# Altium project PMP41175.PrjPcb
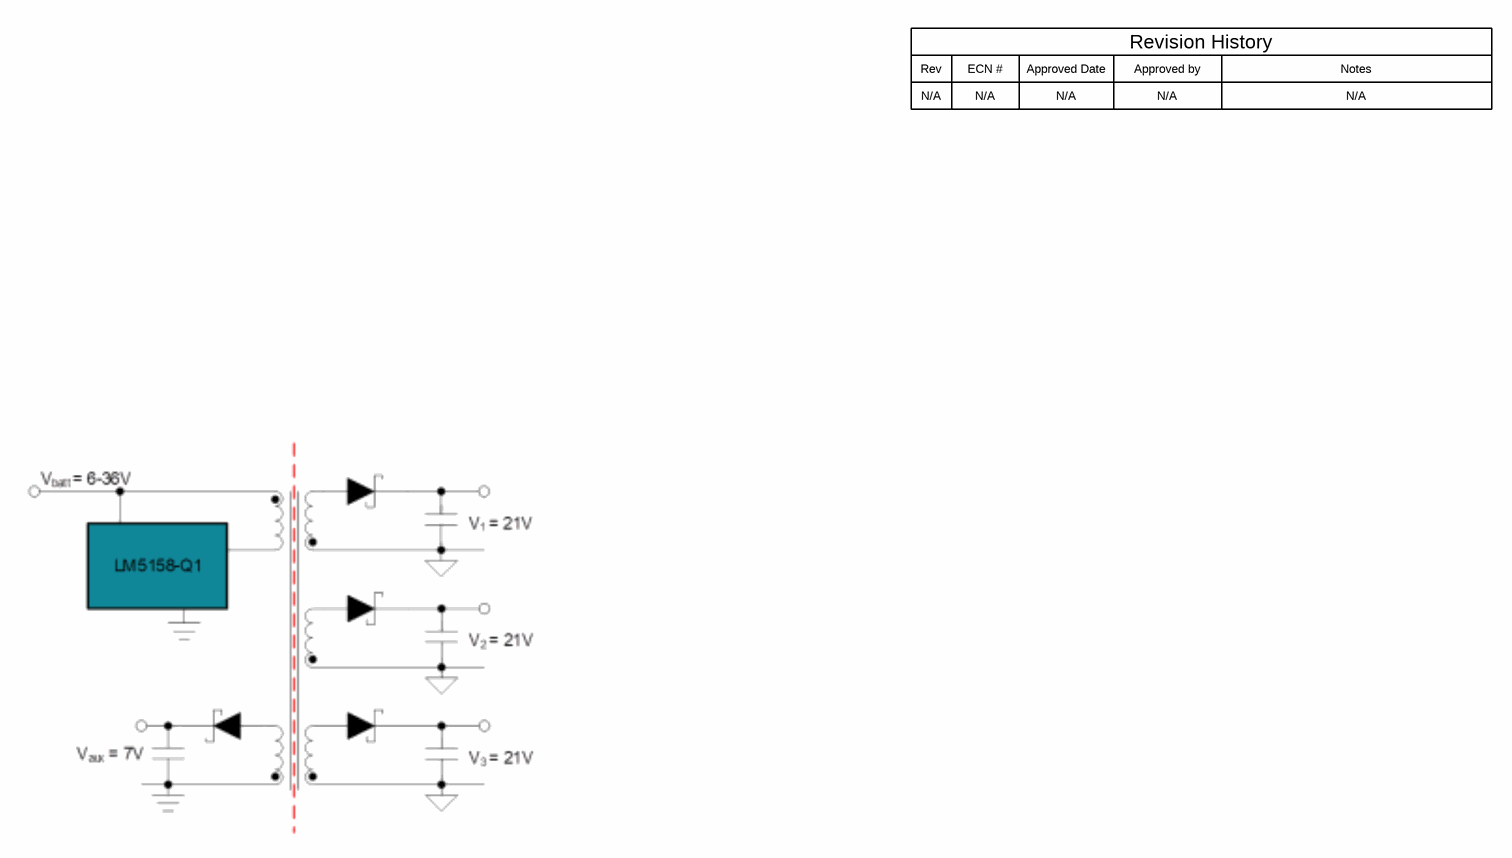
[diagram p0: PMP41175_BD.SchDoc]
CopyrightYear: 2025; PCB_Layout: Helmlinger; PCB_Rev: E1; PRJ_Customer: Public Release; PRJ_Engineer: Helmlinger; PRJ_Number: PMP41175; PRJ_Title: Flyback with planar XFMR; SCH_Rev: E1; TechSupport: http://www.ti.com/support; TID: N/A
3 sheets, 58 parts. Net scope: global (net labels, ports and power ports of the same name join across sheets).
Board file: PMP41175.PcbDoc
Sheets:
  PMP41175_BD.SchDoc
  PMP41175_Sheet1.SchDoc
  PMP41175_Hardware.SchDoc

## Sheet PMP41175_BD.SchDoc
size 431 x 279 mm; Date: Not shown in title block; ApprovedBy: Not shown in title block; CheckedBy: Not shown in title block; Author: Not shown in title block; CompanyName: Not shown in title block; Engineer: Not shown in title block; Organization: Not shown in title block; Address1: Not shown in title block; Address2: Not shown in title block; Address3: Not shown in title block; Address4: Not shown in title block; DocumentNumber: 1; Revision: Use project parameter SCH_Rev; SheetNumber: 1; SheetTotal: 3; PageSetup: Record=PageOptions¦CenterHorizontal=True¦CenterVertical=True¦PrintScale=1.00¦XCorrection=1.00¦YCorrection=1.00¦PrintKind=0¦BorderSize=5000000¦LeftOffset=0¦BottomOffset=0¦Orientation=2¦PaperLength=1000¦PaperWidth=1000¦Scale=100¦PaperSource=15¦PrintQuality=600¦MediaType=1¦DitherType=10¦PaperKind=Letter¦PrintScaleMode=1

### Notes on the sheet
- Rev
- N/A
- ECN #
- Approved Date
- Approved by
- Revision History
- Notes

## Sheet PMP41175_Sheet1.SchDoc
size 431 x 279 mm; Date: Not shown in title block; ApprovedBy: Not shown in title block; CheckedBy: Not shown in title block; Author: Not shown in title block; CompanyName: Not shown in title block; Engineer: Not shown in title block; Organization: Not shown in title block; Address1: Not shown in title block; Address2: Not shown in title block; Address3: Not shown in title block; Address4: Not shown in title block; DocumentNumber: 2; Revision: Use project parameter SCH_Rev; SheetNumber: 2; SheetTotal: 3; PageSetup: Record=PageOptions¦CenterHorizontal=True¦CenterVertical=True¦PrintScale=1.00¦XCorrection=1.00¦YCorrection=1.00¦PrintKind=0¦BorderSize=5000000¦LeftOffset=0¦BottomOffset=0¦Orientation=2¦PaperLength=1000¦PaperWidth=1000¦Scale=100¦PaperSource=15¦PrintQuality=600¦MediaType=1¦DitherType=10¦PaperKind=Letter¦PrintScaleMode=1
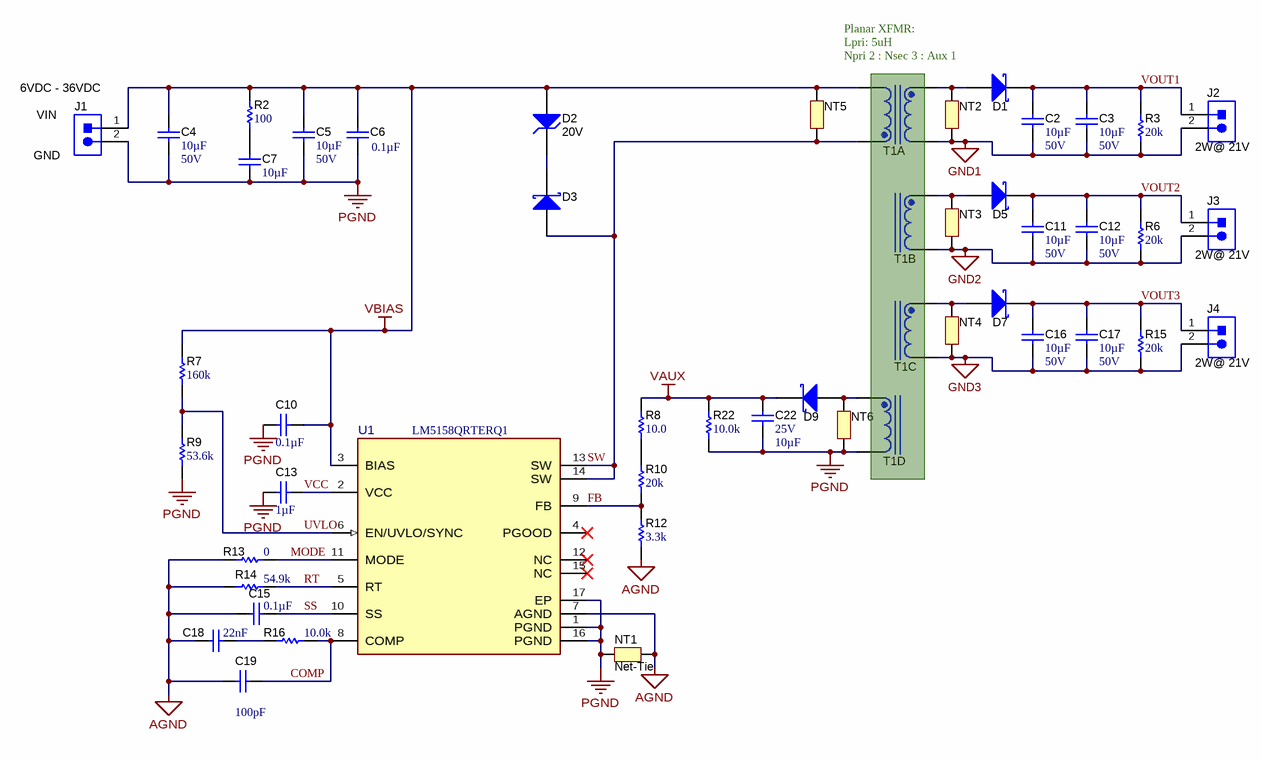
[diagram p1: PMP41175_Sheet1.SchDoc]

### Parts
C2  ValueDisplayed: 10µF  VDC_V: 50V  [1206_190]  (hidden comment: CGA5L1X7R1H106K160AC)
C3  ValueDisplayed: 10µF  VDC_V: 50V  [1206_190]  (hidden comment: CGA5L1X7R1H106K160AC)
C4  ValueDisplayed: 10µF  VDC_V: 50V  [1206_190]  (hidden comment: CGA5L1X7R1H106K160AC)
C5  ValueDisplayed: 10µF  VDC_V: 50V  [1206_190]  (hidden comment: CGA5L1X7R1H106K160AC)
C6  ValueDisplayed: 0.1µF  [0603L]  (hidden comment: C0603C104K5RACAUTO)
C7  ValueDisplayed: 10µF  [1206_190]  (hidden comment: CGA5L1X7R1H106K160AC)
C10  ValueDisplayed: 0.1µF  [0603L]  (hidden comment: C0603C104K5RACAUTO)
C11  ValueDisplayed: 10µF  VDC_V: 50V  [1206_190]  (hidden comment: CGA5L1X7R1H106K160AC)
C12  ValueDisplayed: 10µF  VDC_V: 50V  [1206_190]  (hidden comment: CGA5L1X7R1H106K160AC)
C13  Cap_F: 1µF  [0603L]  (hidden comment: 06033C105KAT2A)
C15  ValueDisplayed: 0.1µF  [0603L]  (hidden comment: C0603C104K5RACAUTO)
C16  ValueDisplayed: 10µF  VDC_V: 50V  [1206_190]  (hidden comment: CGA5L1X7R1H106K160AC)
C17  ValueDisplayed: 10µF  VDC_V: 50V  [1206_190]  (hidden comment: CGA5L1X7R1H106K160AC)
C18  Cap_F: 22nF  [0603L]  (hidden comment: C0603C223K3RACTU)
C19  ValueDisplayed: 100pF  [0603L]  (hidden comment: GCM1885C1H101JA16J)
C22  VDC_V: 25V  ValueDisplayed: 10µF  [0603L]  (hidden comment: GRM188R61E106KA73D)
D1  PMEG10020ELRX  [SOD-123W]  (value not drawn)
D2  value 20V  [SMA]  (hidden comment: 3SMAJ5932B-TP)
D3  PMEG60T30ELRX  [SOD-123W]  (value not drawn)
D5  PMEG10020ELRX  [SOD-123W]  (value not drawn)
D7  PMEG10020ELRX  [SOD-123W]  (value not drawn)
D9  PMEG10020ELRX  [SOD-123W]  (value not drawn)
J1  HTSW-102-09-G-S  [Samtec_HTSW-102-09-x-S]  (value not drawn)
J2  HTSW-102-09-G-S  [Samtec_HTSW-102-09-x-S]  (value not drawn)
J3  HTSW-102-09-G-S  [Samtec_HTSW-102-09-x-S]  (value not drawn)
J4  HTSW-102-09-G-S  [Samtec_HTSW-102-09-x-S]  (value not drawn)
NT1  Net-Tie  [Net-Tie_10mil]  (net tie, no BOM)
NT2  Net-Tie  [Net-Tie_10mil]  (value not drawn)  (net tie, no BOM)
NT3  Net-Tie  [Net-Tie_10mil]  (value not drawn)  (net tie, no BOM)
NT4  Net-Tie  [Net-Tie_10mil]  (value not drawn)  (net tie, no BOM)
NT5  Net-Tie  [Net-Tie_10mil]  (value not drawn)  (net tie, no BOM)
NT6  Net-Tie  [Net-Tie_10mil]  (value not drawn)  (net tie, no BOM)
R2  ValueDisplayed: 100  [0603L]  (hidden comment: CRCW0603100RFKEA)
R3  ValueDisplayed: 20k  [0603L]  (hidden comment: RC0603JR-0720KL)
R6  ValueDisplayed: 20k  [0603L]  (hidden comment: RC0603JR-0720KL)
R7  ValueDisplayed: 160k  [0603L]  (hidden comment: RC0603FR-07160KL)
R8  ValueDisplayed: 10.0  [0603L]  (hidden comment: RC0603FR-0710RL)
R9  ValueDisplayed: 53.6k  [0603L]  (hidden comment: RC0603FR-0753K6L)
R10  ValueDisplayed: 20k  [0603L]  (hidden comment: RC0603JR-0720KL)
R12  ValueDisplayed: 3.3k  [0603L]  (hidden comment: RC0603JR-073K3L)
R13  ValueDisplayed: 0  [0603L]  (hidden comment: ERJ-3GEY0R00V)
R14  ValueDisplayed: 54.9k  [0603L]  (hidden comment: RC0603FR-0754K9L)
R15  ValueDisplayed: 20k  [0603L]  (hidden comment: RC0603JR-0720KL)
R16  ValueDisplayed: 10.0k  [0603L]  (hidden comment: RC0603FR-0710KL)
R22  ValueDisplayed: 10.0k  [0603L]  (hidden comment: RC0603FR-0710KL)
T1  750345026  [PMP41104 Transformer]  (value not drawn)  (parts A,B,C,D of 5)
U1  LM5158QRTERQ1  [RTE0016K-MFG]

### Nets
AGND: C15.2 C18.2 C19.2 NT1.2 R12.1 R13.1 R14.1 U1.7(AGND)
GND1: C2.2 C3.2 J2.2 NT2.1 R3.1 T1.8
GND2: C11.2 C12.2 J3.2 NT3.1 R6.1 T1.14
GND3: C16.2 C17.2 J4.2 NT4.1 R15.1 T1.12
PGND: C4.2 C5.2 C6.2 C7.2 C10.2 C13.2 C22.2 J1.2 NT1.1 NT6.1 R9.2 R22.1 T1.6 U1.1(PGND) U1.16(PGND) U1.17(EP)
VAUX: C22.1 D9.1(K) R8.1 R22.2
VBIAS: C4.1 C5.1 C6.1 C10.1 D2.2(A) J1.1 NT5.2 R2.2 R7.1 T1.4 U1.3(BIAS)
COMP: C19.1 R16.2 U1.8(COMP)
FB: R10.1 R12.2 U1.9(FB)
MODE: R13.2 U1.11(MODE)
RT: R14.2 U1.5(RT)
SS: C15.1 U1.10(SS)
SW: D3.2(A) NT5.1 T1.2 U1.13(SW) U1.14(SW)
UVLO: R7.2 R9.1 U1.6(EN/UVLO/SYNC)
VCC: C13.1 U1.2(VCC)
VOUT1: C2.1 C3.1 D1.1(K) J2.1 R3.2
VOUT2: C11.1 C12.1 D5.1(K) J3.1 R6.2
VOUT3: C16.1 C17.1 D7.1(K) J4.1 R15.2
NetC7_1: C7.1 R2.1
NetC18_1: C18.1 R16.1
NetD1_2: D1.2(A) NT2.2 T1.7
NetD2_1: D2.1(K) D3.1(K)
NetD5_2: D5.2(A) NT3.2 T1.15
NetD7_2: D7.2(A) NT4.2 T1.13
NetD9_2: D9.2(A) NT6.2 T1.11
NetR8_2: R8.2 R10.2

Not connected (* = marked no-connect by the designer): U1 4(PGOOD)* 12(NC)* 15(NC)*

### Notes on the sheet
- (near J1) VIN
- (near J1) 6VDC - 36VDC
- (near T1) Planar XFMR:
  Lpri: 5uH
  Npri 2 : Nsec 3 : Aux 1
- (near J1) GND
- (near J2) 2W@ 21V
- (near J3) 2W@ 21V
- (near J4) 2W@ 21V

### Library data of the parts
C2-C5 C11 C12 C16 C17 = CMP-0085950-1: CAP, CERM, 10 µF, 50 V,+/- 10%, X7R, AEC-Q200 Grade 1, 1206; Manufacturer: TDK; SizeZ_mm: 1.9; Value: 10uF; Cap_Case: 1206; AEC Grade: 1; TaMin_C: -55°C; U/M: EA; SizeArea_mm2: 5.12; TaMax_C: 125°C; AEC Qualified: Y; AEC Category: Q200; SizeX_mm: 3.2; SizeY_mm: 1.6; Polarized: N; SizeAreaWB_mm2: 10.92
C6 C10 C15 = CMP-0079602-1: CAP, CERM, 0.1 µF, 50 V,+/- 10%, X7R, AEC-Q200 Grade 1, 0603; Manufacturer: Kemet; TaMin_C: -55°C; Polarized: N; SizeAreaWB_mm2: 4.68; U/M: EA; Value: 0.1uF; TaMax_C: 125°C; SizeZ_mm: 1; SizeX_mm: 1.6; SizeY_mm: 0.8; Cap_Case: 0603; Value2: 50V; SizeArea_mm2: 1.28; AEC Qualified: Y; Cap_F: 100nF; AEC Category: Q200
C7 = CMP-0085950-1: CAP, CERM, 10 µF, 50 V,+/- 10%, X7R, AEC-Q200 Grade 1, 1206; Manufacturer: TDK; SizeZ_mm: 1.9; Value: 10uF; Value2: 50V; Cap_Case: 1206; AEC Grade: 1; TaMin_C: -55°C; U/M: EA; SizeArea_mm2: 5.12; TaMax_C: 125°C; AEC Qualified: Y; AEC Category: Q200; SizeX_mm: 3.2; SizeY_mm: 1.6; Polarized: N; SizeAreaWB_mm2: 10.92
C13 = CMP-0006754-4: CAP, CERM, 1 uF, 25 V, +/- 10%, X7R, 0603; Manufacturer: AVX; TaMin_C: -55°C; Polarized: N; SizeAreaWB_mm2: 4.68; U/M: EA; Value: 1uF; TaMax_C: 125°C; SizeZ_mm: 1; SizeX_mm: 1.6; SizeY_mm: 0.8; Cap_Case: 0603; Value2: 25V; SizeArea_mm2: 1.28; AEC Category: Q200; Value1: Unknown
C18 = CMP-0006899-4: CAP, CERM, 0.022 uF, 25 V, +/- 10%, X7R, 0603; Manufacturer: Kemet; TaMin_C: -55°C; Polarized: N; SizeAreaWB_mm2: 4.68; Value1: Unknown; U/M: EA; TaMax_C: 125°C; SizeZ_mm: 1; SizeX_mm: 1.6; SizeY_mm: 0.8; Cap_Case: 0603; Value2: 25V; SizeArea_mm2: 1.28; AEC Category: Q200
C19 = CMP-0750041-1: CAP, CERM, 100 pF, 50 V,+/- 5%, C0G/NP0, AEC-Q200 Grade 1, 0603; Manufacturer: MuRata; AEC Grade: 1; SizeArea_mm2: 1.28; SizeX_mm: 1.6; Polarized: N; Cap_Case: 0603; TaMax_C: 125°C; Value2: 50V; Value: 100pF; U/M: EA; AEC Qualified: Y; SizeAreaWB_mm2: 4.68; TaMin_C: -55°C; SizeY_mm: 0.8; AEC Category: Q200
C22 = CMP-0860569-1: CAP, CERM, 10 µF, 25 V,+/- 10%, X5R, 0603; Manufacturer: MuRata; SizeZ_mm: 1; AEC Category: Q200; AEC Qualified: N; TaMin_C: -55°C; Cap_Case: 0603; SizeY_mm: 0.8; SizeAreaWB_mm2: 4.68; SizeArea_mm2: 1.28; TaMax_C: 85°C; SizeX_mm: 1.6; Value: 10uF; U/M: EA
D1 D5 D7 D9 = CMP-0028977-2: Diode, Schottky, 100 V, 2 A, AEC-Q101, SOD-123W; Manufacturer: Nexperia; SizeY_mm: 1.7; Value2: 0.83V; Vf_V: 830mV; SizeZ_mm: 1; SizeAreaWB_mm2: 12.15; Value1: 2A; Vr_V: 100V; TJmax_C: 175°C; SizeArea_mm2: 5.95; AEC Category: Q101; AEC Qualified: Y; Value: 100V; SizeX_mm: 3.5
D2 = CMP-0005511-4: Diode, Zener, 20 V, 3 W, SMA; Manufacturer: Micro Commercial Components; SizeArea_mm2: 16.3228; Power_W: 3W; SizeAreaWB_mm2: 37.3428; SizeY_mm: 2.92; AEC Category: Q101; RJA_CperW: 226; SizeZ_mm: 2.87; SizeX_mm: 5.59
D3 = CMP-0085903-1: Diode, Schottky, 60 V, 3 A, AEC-Q101, SOD-123W; Manufacturer: Nexperia; Vr_V: 60V; Value1: 3A; TJmax_C: 175°C; Value: 60V; SizeY_mm: 1.7; SizeZ_mm: 1; Vf_V: 620mV; SizeArea_mm2: 5.95; SizeX_mm: 3.5; Value2: 0.62V; SizeAreaWB_mm2: 12.15; AEC Category: Q101; AEC Qualified: Y
J1-J4 = CMP-0075626-1: Header, 100mil, 2x1, Gold, TH; Manufacturer: Samtec; Pitch_mm: 2.54; Gender: Male; Cert_CSA: Y; CT: False; Row_Count: 1
NT1-NT6 = CMP-0078142-6: Single point connection between nets.
R2 = CMP-0021991-4: RES, 100, 1%, 0.1 W, AEC-Q200 Grade 0, 0603; Manufacturer: Vishay-Dale; Power_W: 100mW; TempCo: 100 ppm/C; Value_Code: 100R; Value: 100; EIA_Code: E96; SizeX_mm: 1.6; SizeY_mm: 0.8; SizeZ_mm: 1; Value2: 0.1W; SizeArea_mm2: 1.28; AEC Qualified: Y; VDC_V: 75V; AEC Category: Q200; AEC Grade: 0
R3 R6 R10 R15 = CMP-0025900-5: RES, 20 k, 5%, 0.1 W, 0603; Manufacturer: Yageo; Power_W: 100mW; TempCo: 100 ppm/C; Value_Code: 20k0; Value: 20k; EIA_Code: E24; SizeX_mm: 1.6; SizeY_mm: 0.8; SizeZ_mm: 1; Value2: 0.1W; SizeArea_mm2: 1.28; AEC Qualified: N; VDC_V: 75V; AEC Category: Q200; SizeAreaWB_mm2: 4.68
R7 = CMP-0022820-4: RES, 160 k, 1%, 0.1 W, 0603; Manufacturer: Yageo; Value: 160k; SizeX_mm: 1.6; SizeY_mm: 0.8; SizeZ_mm: 1; Value2: 0.1W; SizeArea_mm2: 1.28; AEC Qualified: N; VDC_V: 75V; AEC Category: Q200; SizeAreaWB_mm2: 4.68; Power_W: 100mW; TempCo: 100 ppm/C
R8 = CMP-0022751-4: RES, 10.0, 1%, 0.1 W, 0603; Manufacturer: Yageo; Power_W: 100mW; TempCo: 100 ppm/C; Value_Code: 10R0; Value: 10.0; EIA_Code: E96; Res_ohm: 10; SizeX_mm: 1.6; SizeY_mm: 0.8; SizeZ_mm: 1; Value2: 0.1W; SizeArea_mm2: 1.28; AEC Qualified: N; VDC_V: 75V; AEC Category: Q200; SizeAreaWB_mm2: 4.68
R9 = CMP-0023176-5: RES, 53.6 k, 1%, 0.1 W, 0603; Manufacturer: Yageo; Power_W: 100mW; TempCo: 100 ppm/C; Value_Code: 53k6; Value: 53.6k; EIA_Code: E96; SizeX_mm: 1.6; SizeY_mm: 0.8; SizeZ_mm: 1; Value2: 0.1W; SizeArea_mm2: 1.28; AEC Qualified: N; VDC_V: 75V; AEC Category: Q200; SizeAreaWB_mm2: 4.68
R12 = CMP-0025918-5: RES, 3.3 k, 5%, 0.1 W, 0603; Manufacturer: Yageo; Power_W: 100mW; TempCo: 100 ppm/C; Value_Code: 3k30; Value: 3.3k; EIA_Code: E24; SizeX_mm: 1.6; SizeY_mm: 0.8; SizeZ_mm: 1; Value2: 0.1W; SizeArea_mm2: 1.28; AEC Qualified: N; VDC_V: 75V; AEC Category: Q200; SizeAreaWB_mm2: 4.68
R13 = CMP-0025874-4: RES, 0, 5%, 0.1 W, AEC-Q200 Grade 0, 0603; Manufacturer: Panasonic; Power_W: 100mW; TempCo: 600 ppm/C; Value_Code: 0000; Value: 0; EIA_Code: E24; SizeX_mm: 1.6; SizeY_mm: 0.8; SizeZ_mm: 1; Value2: 0.1W; SizeArea_mm2: 1.28; AEC Qualified: Y; VDC_V: 50V; AEC Category: Q200; SizeAreaWB_mm2: 4.68
R14 = CMP-0023180-5: RES, 54.9 k, 1%, 0.1 W, 0603; Manufacturer: Yageo; Power_W: 100mW; TempCo: 100 ppm/C; Value_Code: 54k9; Value: 54.9k; EIA_Code: E96; SizeX_mm: 1.6; SizeY_mm: 0.8; SizeZ_mm: 1; Value2: 0.1W; SizeArea_mm2: 1.28; AEC Qualified: N; VDC_V: 75V; AEC Category: Q200; SizeAreaWB_mm2: 4.68
R16 R22 = CMP-0022746-5: RES, 10.0 k, 1%, 0.1 W, 0603; Manufacturer: Yageo; Power_W: 100mW; TempCo: 100 ppm/C; Value_Code: 10k0; Value: 10.0k; EIA_Code: E96; Res_ohm: 10k; SizeX_mm: 1.6; SizeY_mm: 0.8; SizeZ_mm: 1; Value2: 0.1W; SizeArea_mm2: 1.28; AEC Qualified: N; VDC_V: 75V; AEC Category: Q200; SizeAreaWB_mm2: 4.68
T1 = XFMR: Manufacturer: Wurth; CompType: Transformer
U1 = CMP-0091836-5: 2.2-MHz Wide VIN 85-V Boost/Sepic/Flyback Converter with Dual Random Spread Spectrum; Manufacturer: Texas Instruments; Output Type: AdjustableProgrammable; Number Of Outputs: 1; Output Voltage: 83V; Standoff Height: 0mm; AEC Qualified: Yes; Max Duty Cycle: 96%; Switching Frequency: 100-2200kHz; AEC Grade: Grade 1; Max Supply Voltage: 60V; TJmax_C: +150°C; Min Supply Voltage: 1.5V; AEC Category: Q200; TaMax_C: +125°C; Nominal Supply Current: 670uA; TaMin_C: -40°C; Switching Topology: Boost,Flyback; SizeZ_mm: 0.8mm; CompType: IC

## Sheet PMP41175_Hardware.SchDoc
size 431 x 279 mm; Date: Not shown in title block; ApprovedBy: Not shown in title block; CheckedBy: Not shown in title block; Author: Not shown in title block; CompanyName: Not shown in title block; Engineer: Not shown in title block; Organization: Not shown in title block; Address1: Not shown in title block; Address2: Not shown in title block; Address3: Not shown in title block; Address4: Not shown in title block; DocumentNumber: 3; Revision: Use project parameter SCH_Rev; SheetNumber: 3; SheetTotal: 3; PageSetup: Record=PageOptions¦CenterHorizontal=True¦CenterVertical=True¦PrintScale=1.00¦XCorrection=1.00¦YCorrection=1.00¦PrintKind=0¦BorderSize=5000000¦LeftOffset=0¦BottomOffset=0¦Orientation=2¦PaperLength=1000¦PaperWidth=1000¦Scale=100¦PaperSource=15¦PrintQuality=600¦MediaType=1¦DitherType=10¦PaperKind=Letter¦PrintScaleMode=1
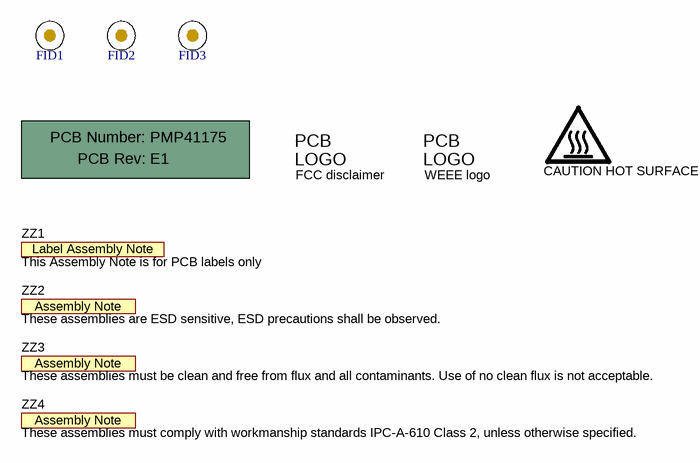
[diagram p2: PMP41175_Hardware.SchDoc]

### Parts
!PCB  Printed Circuit Board  (value not drawn)  (mechanical)
FID1  Fiducial  [Fiducial10-20]  (value not drawn)
FID2  Fiducial  [Fiducial10-20]  (value not drawn)
FID3  Fiducial  [Fiducial10-20]  (value not drawn)
Logo1  CAUTION HOT SURFACE  [IEC_HotSurface_Small]  (no BOM)
Logo3  FCC disclaimer  [FCC_disclaimer]  (no BOM)
Logo4  WEEE logo  [WEEE_Minimum]  (no BOM)
ZZ1  This Assembly Note is for PCB labels only  [AssemblyNoteLabel]  (no BOM)
ZZ2  These assemblies are ESD sensitive, ESD precautions shall be observed.  [AssemblyNote]  (no BOM)
ZZ3  These assemblies must be clean and free from flux and all contaminants. Use of no clean flux is not acceptable.  [AssemblyNote]  (no BOM)
ZZ4  These assemblies must comply with workmanship standards IPC-A-610 Class 2, unless otherwise specified.  [AssemblyNote]  (no BOM)

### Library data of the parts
!PCB = CMP-0003618-2: Manufacturer: Any; PartNumber: PMP41175
FID1-FID3 = CMP-0077181-1: Fiducial mark.  There is nothing to buy or mount.
Logo1 = CMP-0074837-2: IEC 61010-1 Hot Surface Warning; Manufacturer: Texas Instruments; SymbolCreator: a0412235; CompType: IC; AEC Category: Q200
Logo3 = CMP-0074847-1: FCC_disclaimer
Logo4 = CMP-0074769-4: Manufacturer: Texas Instruments; CompType: IC; AEC Category: Q200
ZZ1 = CMP-0003616-3
ZZ2 = CMP-0077236-1
ZZ3 = CMP-0077237-1
ZZ4 = CMP-0077238-1

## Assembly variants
001: not fitted FID1 FID2 FID3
